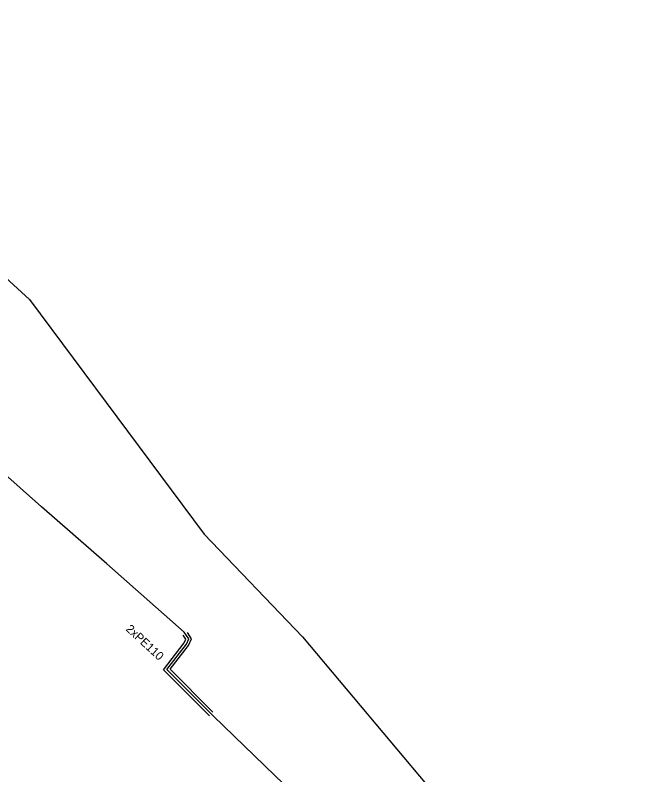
# Model space of a CAD drawing. Extents: x -731967 to -723173, y -945358 to -941505.
# Drawn here: x -725937.8 to -725862.1, y -942281.8 to -942192.1 of the extents above; entities that cross this region are included whole.
import ezdxf

# ---------------------------------------------------------------- set-up
doc = ezdxf.new("R2010")
doc.units = 0
for name, color, linetype in [('Vrstva 2', 7, 'Continuous'), ('Vrstva 28', 7, 'Continuous'), ('Vrstva 35', 7, 'Continuous')]:
    doc.layers.add(name, color=color, linetype=linetype)

msp = doc.modelspace()

# ---------------------------------------------------------------- linework, layer by layer
at = {"layer": 'Vrstva 2'}
for points in [[(-725914.857, -942274.847), (-725920.288, -942269.406), (-725917.829, -942266.215), (-725917.64, -942265.795), (-725917.934, -942265.338)], [(-725914.857, -942274.847), (-725920.288, -942269.406), (-725917.829, -942266.215), (-725917.64, -942265.795), (-725917.934, -942265.338)], [(-725914.432, -942274.423), (-725919.492, -942269.354), (-725917.311, -942266.525), (-725916.96, -942265.745), (-725917.429, -942265.014)], [(-725914.432, -942274.423), (-725919.492, -942269.354), (-725917.311, -942266.525), (-725916.96, -942265.745), (-725917.429, -942265.014)]]:
    msp.add_lwpolyline(points, dxfattribs=at)
at = {"layer": 'Vrstva 28'}
msp.add_lwpolyline([(-725862.08, -942327.44), (-725866.4, -942322.61), (-725873.98, -942314.54), (-725876.66, -942311.52), (-725885.15, -942302.9), (-725886.71, -942301.62), (-725889.6, -942298.75), (-725896.94, -942291.72), (-725897.69, -942290.94), (-725907.13, -942281.91), (-725914.38, -942274.9), (-725919.89, -942269.38), (-725917.57, -942266.37), (-725917.3, -942265.77), (-725917.82, -942264.96), (-725926.95, -942256.88), (-725934.67, -942250.17), (-725946.58, -942239.58)], dxfattribs=at)
msp.add_lwpolyline([(-725862.08, -942327.44), (-725866.4, -942322.61), (-725873.98, -942314.54), (-725876.66, -942311.52), (-725885.15, -942302.9), (-725886.71, -942301.62), (-725889.6, -942298.75), (-725896.94, -942291.72), (-725897.69, -942290.94), (-725907.13, -942281.91), (-725914.38, -942274.9), (-725919.89, -942269.38), (-725917.57, -942266.37), (-725917.3, -942265.77), (-725917.82, -942264.96), (-725926.95, -942256.88), (-725934.67, -942250.17), (-725946.58, -942239.58)], dxfattribs=at)
at = {"layer": 'Vrstva 35'}
for p, q in [((-725972.925, -942192.117), (-725936.093, -942225.668)), ((-725936.093, -942225.668), (-725915.474, -942253.404)), ((-725915.474, -942253.404), (-725903.865, -942265.52)), ((-725903.865, -942265.52), (-725871.203, -942304.447))]:
    msp.add_line(p, q, dxfattribs=at)

# ---------------------------------------------------------------- texts
at = {"layer": 'Vrstva 2'}
msp.add_text('2xPE110', height=1, rotation=317.23364, dxfattribs=at).set_placement((-725924.795, -942264.695))
msp.add_text('2xPE110', height=1, rotation=317.23364, dxfattribs=at).set_placement((-725924.795, -942264.695))

doc.saveas('drawing.dxf')
